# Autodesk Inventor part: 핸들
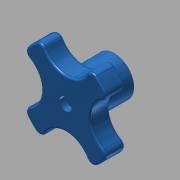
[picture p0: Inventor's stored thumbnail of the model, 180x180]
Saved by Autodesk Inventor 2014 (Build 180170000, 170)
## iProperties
Created: 2018-01
Part Number: 핸들
Material: ABS 플라스틱
Document SubType Name: Modeling
Designer: mduedu
Density: 1 g/cm^3
Appearance: 청록색
Author: mduedu
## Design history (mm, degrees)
sketch "스케치1"
  geometry: C1 r 10 at (0, 0); C2 r 25 at (0, 0); 1 further point
  constraints: 2 centre point, 2 coincident
  dimensions: "d0" = 20 diameter of C1; "d1" = 50 diameter of C2
extrude "돌출1" new body sketch "스케치1" distance "d2" = 15; taper "d3" = 0 deg
extrude "돌출2" join sketch "스케치1" distance "d4" = 10; taper "d5" = 0 deg
sketch "스케치2" dims "d8" = 15
  geometry: L1 (-6, -6)-(-4.5, -6); L2 (6, -6)-(6, -4.5); L3 (6, 6)-(4.5, 6); L4 (-6, 6)-(-6, 4.5); L5 (-6, -6)-(6, 6); L6 (6, -6)-(-6, 6); L7 (-4.5, 6)-(-6, 6); L8 (4.5, 6)-(-4.5, 6); L9 (6, 4.5)-(6, 6); L10 (6, -4.5)-(6, 4.5); L11 (4.5, -6)-(6, -6); L12 (-4.5, -6)-(4.5, -6); L13 (-6, -4.5)-(-6, -6); L14 (-6, 4.5)-(-6, -4.5); 2 further points
  constraints: 28 end point, 18 parallel, 9 perpendicular, 3 horizontal, 2 midpoint, 1 coincident, 10 other
  dimensions: "d6" = 12 distance of L4.start L3.start; "d7" = 12 distance of L3.start L2.start
extrude "돌출3" cut sketch "스케치2" distance "d9" = 15; taper "d10" = 0 deg
sketch "스케치3"
  geometry: C1 r 12.5 at (25, 0); 2 further points
  constraints: 2 horizontal alignment, 1 centre point, 1 other
  dimensions: "d14" = 25 diameter of C1
extrude "돌출4" cut sketch "스케치3" stored distance "d15" = 15; taper "d16" = 0 deg
fillet "모깎기1" dims "d20" = 3
fillet "모깎기2" dims "d24" = 1
sketch "스케치4"
  geometry: 2 further points
  constraints: 1 coincident
sketch "스케치5"
  geometry: 2 further points
  constraints: 1 coincident
hole "구멍1" sketch "스케치5" at (0, 0) diameter "d25" = 3.4; stored, may be unused: countersink angle "d29" = 90 deg, drill point angle "d31" = 0 deg; dims "d26" = 6, "d27" = 6.5, "d28" = 3.4, "d30" = 8
node "솔리드1"
pattern_circular "원형 패턴1" dims angle "d18" = 360 deg
pattern_circular "원형 패턴2" dims angle "d22" = 360 deg
node "투영된 루프1"
